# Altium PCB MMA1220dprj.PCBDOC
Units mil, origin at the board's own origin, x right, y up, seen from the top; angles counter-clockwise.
Board outline 850 x 615 mil, 2 copper layers (Top Layer, Bottom Layer); 5 components, 6 nets, 27 pads, 0 vias.
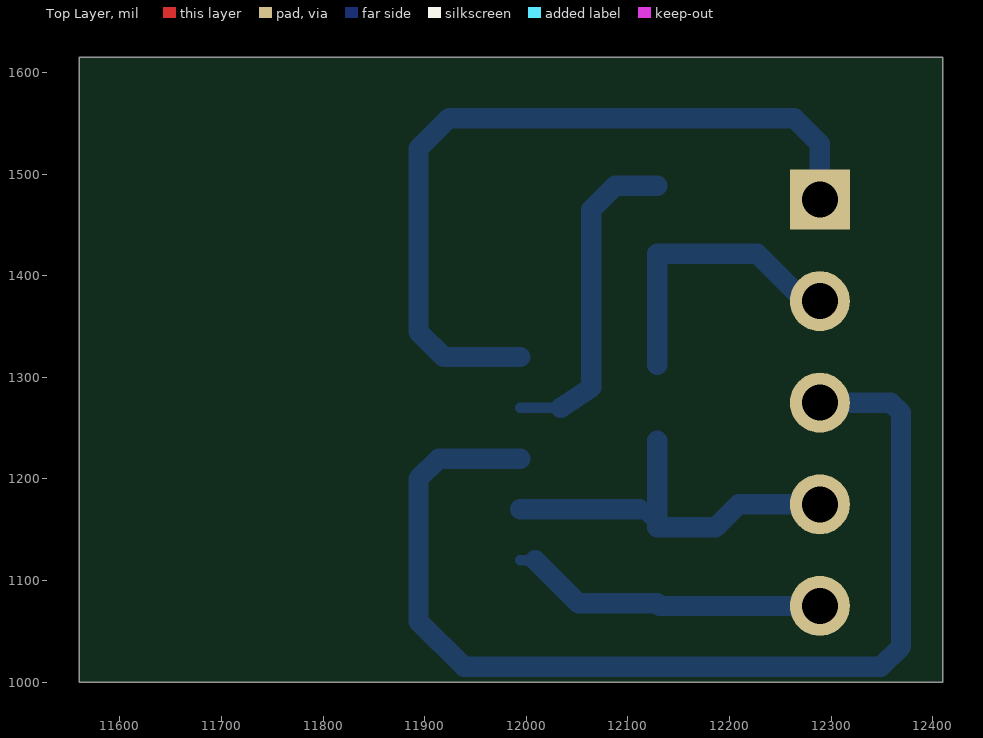
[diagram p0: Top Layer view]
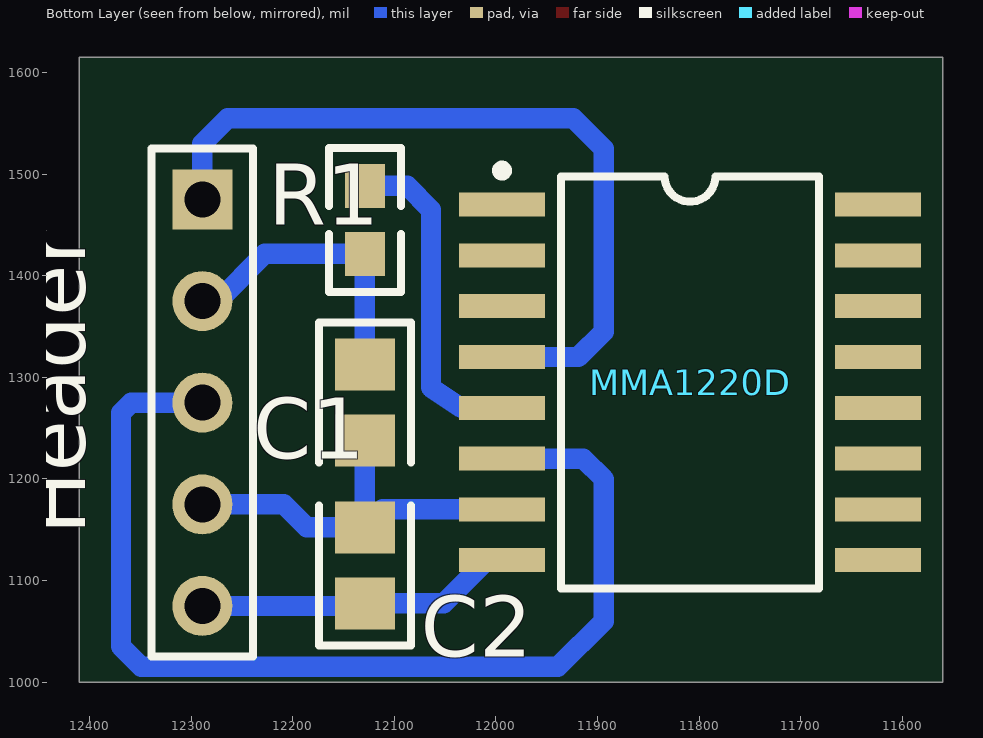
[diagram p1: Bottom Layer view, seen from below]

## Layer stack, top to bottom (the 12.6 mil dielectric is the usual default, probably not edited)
Top Layer: signal copper 1.4
Dielectric: core 12.6, FR-4, Dk 4.8
Bottom Layer: signal copper 1.4

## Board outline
11560,1610 11560,1000 12410,1000 12410,1615 11560,1615

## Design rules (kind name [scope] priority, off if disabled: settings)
RoomDefinition MMA1220Dsch [InComponentClass('MMA1220Dsch')] p1: confinementstyle=ConfineIn formatcopy=TRUE outline 11560,1000 12410,1000 12410,1615 11560,1615

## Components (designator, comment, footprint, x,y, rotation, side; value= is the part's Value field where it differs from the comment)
C1 "Cap Pol3" CC2012-0805 12128.87,1275 r270 bottom
C2 "Cap Pol3" CC2012-0805 12128.87,1115 r90 bottom
Header "Header 5" HDR1X5 12288.87,1475 r270 bottom
MMA1220D "MMA1220D" SO-G16/D10.3 11808.87,1295 r270 bottom (schematic designator *)
R1 "Res3" C1608-0603 12128.87,1455 r270 bottom

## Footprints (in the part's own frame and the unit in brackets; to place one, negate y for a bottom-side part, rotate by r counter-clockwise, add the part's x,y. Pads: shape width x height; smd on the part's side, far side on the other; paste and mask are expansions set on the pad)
C1608-0603 [mm]
  rect 1.1x1 smd: 1(-0.85,0) 2(0.85,0)
  silkscreen extent -1.8,-0.9 1.8,0.9
CC2012-0805 [mm]
  rect 1.3x1.5 smd: 1(-0.95,0) 2(0.95,0)
  silkscreen extent -2,-1.15 1.5,1.15
HDR1X5 [mm] "Connector; Header; 5 Position"
  rect 1.5x1.5 hole 0.9: 1(0,0)
  round 1.5 hole 0.9: 2(2.54,0) 3(5.08,0) 4(7.62,0) 5(10.16,0)
  silkscreen extent -1.27,-1.27 11.43,1.27
SO-G16/D10.3 [mm]
  rect 0.6x2.15 smd: 1(-4.445,-4.7) 2(-3.175,-4.7) 3(-1.905,-4.7) 4(-0.635,-4.7) 5(0.635,-4.7) 6(1.905,-4.7) 7(3.175,-4.7) 8(4.445,-4.7) 9(4.445,4.7) 10(3.175,4.7) 11(1.905,4.7) 12(0.635,4.7) 13(-0.635,4.7) 14(-1.905,4.7) 15(-3.175,4.7) 16(-4.445,4.7)
  silkscreen extent -5.42,-4.82 5.15,3.22

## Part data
C1 C2: "Polarized Capacitor (Surface Mount)"
Header: "Header, 5-Pin"
R1: "Resistor"

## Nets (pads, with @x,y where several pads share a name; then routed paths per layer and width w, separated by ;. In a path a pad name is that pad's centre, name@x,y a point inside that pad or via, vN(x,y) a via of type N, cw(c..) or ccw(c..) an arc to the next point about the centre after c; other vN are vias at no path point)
Net*_4: Header.1 MMA1220D.4 | length 763.2
  Bottom Layer w20: MMA1220D.4 11918.87,1320 11893.87,1345 11893.87,1525 11923.87,1555 12263.87,1555 12288.87,1530 Header.1
Net*_5: MMA1220D.5 R1.1 | length 325.7
  Bottom Layer w10: MMA1220D.5 MMA1220D.5@12033.87,1270
  Bottom Layer w20: MMA1220D.5@12033.87,1270 12063.87,1290 12063.87,1465 12087.34,1488.46 R1.1
Net*_6: Header.3 MMA1220D.6 | length 1064.4
  Bottom Layer w20: MMA1220D.6 11913.87,1220 11893.87,1200 11893.87,1060 11938.87,1015 12348.87,1015 12368.87,1035 12368.87,1265 12358.87,1275 Header.3
Net*_7: C1.2 C2.2 Header.4 MMA1220D.7 | length 396.8
  Bottom Layer w10: C2.2@12111.28,1170 C2.2
  Bottom Layer w20: MMA1220D.7 C2.2@12111.28,1170 ; C1.2 C2.2 12186.28,1152.4 12208.87,1175 Header.4
Net*_8: C2.1 Header.5 MMA1220D.8 | length 313.6
  Bottom Layer w10: MMA1220D.8 MMA1220D.8@12008.87,1120 ; C2.1 C2.1@12131.47,1075
  Bottom Layer w20: MMA1220D.8@12008.87,1120 12051.28,1077.6 C2.1 ; C2.1@12131.47,1075 Header.5
NetC1_1: C1.1 Header.2 R1.2 | length 288.4
  Bottom Layer w10: Header.2@12273.87,1375 Header.2
  Bottom Layer w20: C1.1 R1.2 12227.34,1421.54 Header.2@12273.87,1375
pads on no net: MMA1220D.1 MMA1220D.2 MMA1220D.3 MMA1220D.9 MMA1220D.10 MMA1220D.11 MMA1220D.12 MMA1220D.13 MMA1220D.14 MMA1220D.15 MMA1220D.16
